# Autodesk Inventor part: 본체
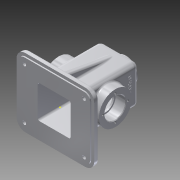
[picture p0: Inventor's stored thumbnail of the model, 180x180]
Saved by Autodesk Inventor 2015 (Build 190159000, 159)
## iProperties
Created: 2016-02
Part Number: 본체
Material: 알루미늄 6061
Document SubType Name: Modeling
Designer: Administrator
Density: 2.7 g/cm^3
Appearance: 알루미늄 - 평지
Mass: 801.895 g
Surface Area: 910.185 cm^2
Volume: 296.998 cm^3
Author: Administrator
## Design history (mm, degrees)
sketch "스케치1"
  geometry: L1 (65, -57.5)-(-65, -57.5); L2 (-65, -57.5)-(-65, 57.5); L3 (-65, 57.5)-(65, 57.5); L4 (65, 57.5)-(65, -57.5); L5 (65, -57.5)-(-65, 57.5); L6 (-65, -57.5)-(65, 57.5); 1 further point
  constraints: 12 end point, 2 midpoint, 2 parallel, 1 horizontal, 1 perpendicular
  dimensions: "d0" = 130 distance of L1.start L1.end; "d1" = 115 distance of L3.end L1.start
extrude "돌출1" new body sketch "스케치1" distance "d2" = 10; taper "d3" = 0 deg
sketch "스케치2"
  geometry: L1 (-65, -57.5)-(65, -57.5) reference; L2 (-65, 57.5)-(-65, -57.5) reference; L3 (65, 57.5)-(-65, 57.5) reference; L4 (65, -57.5)-(65, 57.5) reference; L5 (-60, 52.5)-(-60, -52.5); L6 (-60, -52.5)-(60, -52.5); L7 (60, -52.5)-(60, 52.5); L8 (60, 52.5)-(-60, 52.5); L9 (-65, -57.5)-(65, -57.5); L10 (65, -57.5)-(65, 57.5); L11 (65, 57.5)-(-65, 57.5); L12 (-65, 57.5)-(-65, -57.5); L13 (-65, -57.5)-(65, 57.5); L14 (65, -57.5)-(-65, 57.5); 1 further point
  constraints: 20 end point, 2 midpoint, 2 parallel, 1 horizontal, 1 perpendicular, 3 other
  dimensions: "d4" = 5 distance between parallel lines of L3 L8
extrude "돌출2" cut sketch "스케치2" distance "d5" = 2; taper "d6" = 0 deg
sketch "스케치3"
  geometry: L1 (-32.5, 32.5)-(32.5, 32.5); L2 (32.5, 32.5)-(32.5, -32.5); L3 (32.5, -32.5)-(-32.5, -32.5); L4 (-32.5, -32.5)-(-32.5, 32.5); L5 (-32.5, 32.5)-(32.5, -32.5); L6 (32.5, 32.5)-(-32.5, -32.5); 1 further point
  constraints: 12 end point, 2 midpoint, 2 parallel, 1 horizontal, 1 perpendicular
  dimensions: "d7" = 65 distance of L1.start L1.end; "d8" = 65 distance of L1.end L2.end
extrude "돌출3" join sketch "스케치3" distance "d9" = 100; taper "d10" = 0 deg
sketch "스케치4"
  geometry: C1 r 20 at (0, 0); 1 further point
  constraints: 1 centre point, 1 coincident
  dimensions: "d11" = 40 diameter of C1
extrude "돌출4" join sketch "스케치4" distance "d12" = 10; taper "d13" = 0 deg
sketch "스케치5"
  geometry: C1 r 27.5 at (45, 0); 1 further point
  constraints: 1 centre point
  dimensions: "d14" = 45 distance of point (0, 0) C1.centre; "d15" = 0 vertical distance of point (0, 0) C1.centre; "d16" = 55 diameter of C1
extrude "돌출5" join sketch "스케치5" stored distance "d17" = 95; taper "d18" = 0 deg
sketch "스케치6"
  geometry: L1 (-10, 52.5)-(-8, 52.5) reference; L2 (-8, 52.5)-(-8, 57.5) reference; L3 (-8, 57.5)-(0, 57.5) reference; L4 (0, 57.5)-(0, 32.5) reference; L5 (0, 32.5)-(100, 32.5) reference; L6 (100, 32.5)-(100, 20) reference; L7 (100, 20)-(110, 20) reference; L8 (110, 20)-(110, -20) reference; L9 (110, -20)-(100, -20) reference; L10 (100, -20)-(100, -32.5) reference; L11 (100, -32.5)-(0, -32.5) reference; L12 (0, -32.5)-(0, -57.5) reference; L13 (0, -57.5)-(-8, -57.5) reference; L14 (-8, -57.5)-(-8, -52.5) reference; L15 (-8, -52.5)-(-10, -52.5) reference; L16 (-10, -52.5)-(-10, 52.5) reference; L17 (0, -47.5)-(92.075, -31.265); L18 (92.075, -31.265)-(0, -31.265); L19 (0, -32.5)-(0, 32.5) reference; 1 further point
  constraints: 4 end point, 2 point on line, 1 horizontal
  dimensions: "d19" = 10 vertical distance of L13.end L17.start; "d20" = 10 deg angle of L13 L17; "d21" = 97.23843 distance of point (0, 0) L17.end
extrude "돌출6" join sketch "스케치6" stored distance "d22" = 10; taper "d23" = 0 deg
sketch "스케치7"
  geometry: 1 further point
sketch "스케치8"
  geometry: L1 (-27.5, -27.5)-(27.5, -27.5); L2 (27.5, -27.5)-(27.5, 27.5); L3 (27.5, 27.5)-(-27.5, 27.5); L4 (-27.5, 27.5)-(-27.5, -27.5); L5 (-27.5, -27.5)-(27.5, 27.5); L6 (27.5, -27.5)-(-27.5, 27.5); 1 further point
  constraints: 12 end point, 2 midpoint, 2 parallel, 1 horizontal, 1 perpendicular
  dimensions: "d24" = 55 distance of L3.end L1.start; "d25" = 55 distance of L2.end L3.end
extrude "돌출7" cut sketch "스케치8" distance "d26" = 105; taper "d27" = 0 deg
sketch "스케치9"
  geometry: L1 (-60, -10)-(-60, -8) reference; L2 (-60, -8)-(-65, -8) reference; L3 (-65, -8)-(-65, 0) reference; L4 (-65, 0)-(-32.5, 0) reference; L5 (-32.5, 0)-(-32.5, 17.5) reference; L6 (-32.5, 17.5)-(-47.5, 17.5) reference; L7 (-47.5, 17.5)-(-47.5, 72.5) reference; L8 (-47.5, 72.5)-(-32.5, 72.5) reference; L9 (-32.5, 72.5)-(-32.5, 100) reference; L10 (-32.5, 100)-(-20, 100) reference; L11 (-20, 100)-(-20, 110) reference; L12 (-20, 110)-(20, 110) reference; L13 (20, 110)-(20, 100) reference; L14 (20, 100)-(32.5, 100) reference; L15 (32.5, 100)-(32.5, 72.5) reference; L16 (32.5, 72.5)-(47.5, 72.5) reference; L17 (47.5, 72.5)-(47.5, 17.5) reference; L18 (47.5, 17.5)-(32.5, 17.5) reference; L19 (32.5, 17.5)-(32.5, 0) reference; L20 (32.5, 0)-(65, 0) reference; L21 (65, 0)-(65, -8) reference; L22 (65, -8)-(60, -8) reference; L23 (60, -8)-(60, -10) reference; L24 (60, -10)-(27.5, -10) reference; L25 (27.5, -10)-(27.5, 95) reference; L26 (27.5, 95)-(-27.5, 95) reference; L27 (-27.5, 95)-(-27.5, -10) reference; L28 (-27.5, -10)-(-60, -10) reference; L29 (-65, 0)-(65, 0) reference; L30 (-42.5, 0)-(-42.5, 26.418); L31 (-42.5, 26.418)-(-29.871, 26.418); L32 (-29.871, 26.418)-(-29.871, 0); 1 further point
  constraints: 6 end point, 2 perpendicular, 2 point on line, 1 horizontal
  dimensions: "d28" = 15 distance between parallel lines of L30 L27; "d29" = 12.62939 distance of L30.end L31.end; "d30" = 26.41756 distance of L30.start L30.end
extrude "돌출8" join sketch "스케치9" stored distance "d31" = 6; taper "d32" = 0 deg
sketch "스케치10"
  geometry: C1 r 15 at (0, 0); A1 r 27.5 centre (0, 0) between (3, -27.336) and (-3, -27.336) reference; A2 r 27.5 centre (0, 0) between (3, -27.336) and (-3, -27.336) reference; 1 further point
  constraints: 1 centre point, 1 concentric
  dimensions: "d33" = 30 diameter of C1
extrude "돌출9" cut sketch "스케치10" stored distance "d34" = 6; taper "d35" = 0 deg
sketch "스케치11"
  geometry: C1 r 17.5 at (0, 0); A1 r 27.5 centre (0, 0) between (3, -27.336) and (-3, -27.336) reference; 1 further point
  constraints: 1 centre point, 1 concentric
  dimensions: "d36" = 35 diameter of C1
extrude "돌출10" cut sketch "스케치11" distance "d37" = 17; taper "d38" = 0 deg
fillet "모깎기1" dims "d39" = 15
fillet "모깎기2" dims "d40" = 10
sketch "스케치12"
  geometry: C1 r 7.5 at (50, 42.5); A1 r 15 centre (50, 42.5) between (65, 42.5) and (50, 57.5) reference; 1 further point
  constraints: 1 centre point, 1 concentric
  dimensions: "d41" = 15 diameter of C1
extrude "돌출11" join sketch "스케치12" distance "d42" = 3; taper "d43" = 0 deg
hole "구멍1" diameter "d46" = 6; stored, may be unused: countersink angle "d50" = 90 deg, drill point angle "d52" = 118 deg; dims "d44" = 10, "d45" = 10, "d47" = 6, "d48" = 4, "d49" = 2, "d51" = 8
fillet "모깎기3" dims "d53" = 8
fillet "모깎기4" dims "d54" = 8
fillet "모깎기5" dims "d55" = 3
fillet "모깎기7" dims "d57" = 3
fillet "모깎기8" dims "d58" = 3
fillet "모깎기9" dims "d59" = 3
fillet "모깎기10" dims "d60" = 1
fillet "모깎기11" dims "d61" = 3
fillet "모깎기12" dims "d62" = 3
sketch "스케치13"
  geometry: L1 (-24.5, -55)-(24.5, -55) reference; 2 further points
  dimensions: "d63" = 0 horizontal distance of point (0, -45) point (0, 21); "d64" = 76 distance from line of L1 point (0, 21)
hole "구멍2" sketch "스케치13" at (0, 21) diameter "d65" = 3.242; stored, may be unused: countersink angle "d69" = 90 deg, drill point angle "d71" = 118 deg; dims "d66" = 8, "d67" = 4, "d68" = 2, "d70" = 10
sketch "스케치14"
  geometry: C1 r 10.5 at (0, 0); C2 r 20 at (0, 0) reference; 1 further point
  constraints: 1 centre point, 1 concentric
  dimensions: "d75" = 21 diameter of C1
extrude "돌출12" cut sketch "스케치14" distance "d76" = 48.5; taper "d77" = 0 deg
sketch "스케치15"
  geometry: 2 further points
  dimensions: "d78" = 0 horizontal distance of point (0, 0) point (0, 14.5); "d79" = 14.5 distance of point (0, 0) point (0, 14.5)
hole "구멍3" sketch "스케치15" at (0, 14.5) diameter "d80" = 2.459; stored, may be unused: countersink angle "d84" = 90 deg, drill point angle "d86" = 118 deg; dims "d81" = 7, "d82" = 4, "d83" = 2, "d85" = 9
sketch "스케치16"
  geometry: 1 further point
sketch "스케치17"
  geometry: L1 (57, -91)-(57, 0) reference; L2 (44.5, 18)-(4.5, 18) reference; 2 further points
  constraints: 1 other
  dimensions: "d90" = 32.5 distance from line of L1 point (24.5, -8); "d91" = 26 distance from line of L2 point (24.5, -8)
feature "엠보싱1" sketch "스케치17" dims "d92" = 0.5, "d93" = 0
fillet "모깎기13" dims "d94" = 0.3
chamfer "모따기1" distance "d95" = 1; stored, may be unused: second distance "d96" = 2, angle "d97" = 45 deg
chamfer "모따기2" distance "d98" = 1; stored, may be unused: second distance "d99" = 2, angle "d100" = 45 deg
fillet "모깎기14" dims "d101" = 3
fillet "모깎기15" dims "d102" = 3
fillet "모깎기16" dims "d103" = 3
node "솔리드1"
mirror "대칭1"
mirror "대칭2"
mirror "대칭3"
mirror "대칭4"
mirror "대칭5"
mirror "대칭6"
mirror "대칭7"
pattern_circular "원형 패턴1" dims angle "d73" = 360 deg
mirror "대칭8"
pattern_circular "원형 패턴2" dims angle "d88" = 360 deg
node "투영된 루프1"
node "절단 모서리 투영1"
node "절단 모서리 투영2"
